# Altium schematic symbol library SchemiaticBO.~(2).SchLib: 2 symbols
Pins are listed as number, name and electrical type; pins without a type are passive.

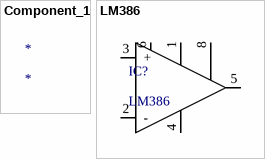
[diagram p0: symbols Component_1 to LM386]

## Component_1
designator *

## LM386
designator IC?
pins: 1, 2 -, 3 +, 4, 5, 6, 8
